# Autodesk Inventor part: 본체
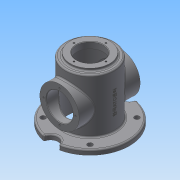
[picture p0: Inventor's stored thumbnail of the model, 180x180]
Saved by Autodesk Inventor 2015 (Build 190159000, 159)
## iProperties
Created: 2018-04
Part Number: 본체
Material: 일반
Document SubType Name: Modeling
Designer: user
Density: 1 g/cm^3
Appearance: 기본값
Mass: 425.882 g
Surface Area: 1203.14 cm^2
Volume: 425.882 cm^3
Author: user
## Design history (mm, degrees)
sketch "스케치2"
  geometry: C1 r 45 at (0, 0); C2 r 50 at (0, 0); 1 further point
  constraints: 2 centre point, 2 coincident
  dimensions: "d0" = 90 diameter of C1; "d1" = 100 diameter of C2
extrude "돌출1" new body sketch "스케치2" distance "d2" = 128; taper "d3" = 0 deg
node "작업 평면1"
sketch "스케치3"
  geometry: L1 (0, 0)-(0, 80); L2 (0, 0)-(0, -80); C1 r 45 at (0, 0); A1 r 15 centre (0, 80) between (-14.934, 78.594) and (14.934, 78.594); A2 r 15 centre (0, -80) between (14.934, -78.594) and (-14.934, -78.594); A3 r 80 centre (0, 0) between (-14.934, 78.594) and (-14.934, -78.594); A4 r 80 centre (0, 0) between (14.934, -78.594) and (14.934, 78.594); A5 r 67.5 centre (0, 0) between (-7.604, 67.07) and (-7.604, -67.07); A6 r 67.5 centre (0, 0) between (7.604, -67.07) and (7.604, 67.07); 1 further point
  constraints: 16 point on circle, 7 centre point, 5 coincident, 4 end point, 2 vertical
  dimensions: "d6" = 90 diameter of C1; "d10" = 30 diameter of A1; "d11" = 30 diameter of A2; "d12" = 80 distance of L1.start L1.end; "d13" = 80 distance of L1.start L2.end; "d14" = 80 radius of A3; "d15" = 67.5 radius of A5; "d16" = 67.5 radius of A6; "d17" = 80 radius of A4
extrude "돌출2" join sketch "스케치3" distance "d18" = 10; taper "d19" = 0 deg
sketch "스케치4"
  geometry: L1 (0, 0)-(-47.73, 47.73); L2 (0, 0)-(-47.73, -47.73); L3 (0, 0)-(0, -36.099); L4 (0, 0)-(47.73, 47.73); L5 (0, 0)-(47.73, -47.73); C1 r 50 at (0, 0) reference; A1 r 67.5 centre (0, 0) between (-47.73, 47.73) and (-47.73, -47.73); 4 further points
  constraints: 10 end point, 5 coincident, 2 point on circle, 2 symmetric about line, 1 centre point, 1 vertical
  dimensions: "d21" = 45 deg angle of L3 L2; "d22" = 90 deg angle of L1 L2; "d23" = 135 diameter of A1
hole "구멍1" sketch "스케치4" at (-47.73, -47.73), (-47.73, 47.73), (47.73, 47.73), (47.73, -47.73) diameter "d24" = 10; stored, may be unused: countersink angle "d28" = 90 deg, drill point angle "d30" = 118 deg; dims "d25" = 6, "d26" = 4, "d27" = 2, "d29" = 8
node "작업 평면2"
sketch "스케치6"
  geometry: C1 r 27 at (0, 0); C2 r 40 at (0, 0); 1 further point
  constraints: 2 centre point, 2 coincident
  dimensions: "d32" = 54 diameter of C1; "d33" = 80 diameter of C2
extrude "돌출3" join sketch "스케치6" distance "d34" = 5; taper "d35" = 0 deg
node "작업 평면3"
sketch "스케치7"
  geometry: C1 r 50 at (0, 0); 1 further point
  constraints: 1 centre point, 1 coincident
  dimensions: "d37" = 100 diameter of C1
extrude "돌출4" join sketch "스케치7" distance "d38" = 8; taper "d39" = 0 deg
extrude "돌출5" cut sketch "스케치6" stored distance "d40" = 8; taper "d41" = 0 deg
node "작업 평면4"
sketch "스케치10"
  geometry: L1 (0, 0)-(0, 68); C1 r 40 at (0, 68); C2 r 27 at (0, 68)
  constraints: 2 centre point, 2 coincident, 2 end point, 1 vertical
  dimensions: "d48" = 68 distance of L1.start L1.end; "d49" = 80 diameter of C1; "d50" = 54 diameter of C2
extrude "돌출6" join sketch "스케치10" stored distance "d51" = 8; taper "d52" = 0 deg
extrude "돌출7" cut sketch "스케치10" stored distance "d53" = 8; taper "d54" = 0 deg
sketch "스케치11"
  geometry: L1 (0, 0)-(0, -32.5); L2 (0, 0)-(32.5, 0); L3 (0, 0)-(-32.5, 0); L4 (0, 0)-(0, 32.5); C1 r 40 at (0, 0) reference; A1 r 32.5 centre (0, 0) between (0, -32.5) and (32.5, 0); 4 further points
  constraints: 8 end point, 5 coincident, 4 point on circle, 2 horizontal, 2 vertical, 1 centre point
  dimensions: "d55" = 65 diameter of A1
hole "구멍2" sketch "스케치11" at (0, -32.5), (-32.5, 0), (0, 32.5), (32.5, 0) diameter "d56" = 3.242; stored, may be unused: countersink angle "d60" = 90 deg, drill point angle "d62" = 118 deg; dims "d57" = 8, "d58" = 4, "d59" = 2, "d61" = 10
sketch "스케치12"
  geometry: L1 (0, 0)-(0, 32.5); L2 (0, 0)-(32.5, 0); L3 (0, 0)-(0, -32.5); L4 (0, 0)-(-32.5, 0); C1 r 40 at (0, 0) reference; A1 r 32.5 centre (0, 0) between (0, 32.5) and (32.5, 0); 5 further points
  constraints: 8 end point, 5 coincident, 4 point on circle, 2 horizontal, 2 vertical, 1 centre point
  dimensions: "d63" = 65 diameter of A1
hole "구멍3" sketch "스케치12" at (0, 32.5), (32.5, 0), (0, -32.5), (-32.5, 0) diameter "d64" = 3.242; stored, may be unused: countersink angle "d68" = 90 deg, drill point angle "d70" = 118 deg; dims "d65" = 8, "d66" = 4, "d67" = 2, "d69" = 10
chamfer "모따기1" distance "d71" = 1; stored, may be unused: second distance "d72" = 2, angle "d73" = 45 deg
fillet "모깎기1" dims "d74" = 3
fillet "모깎기2" dims "d75" = 3
node "작업 평면5"
sketch "스케치13"
  geometry: 2 further points
  constraints: 1 horizontal alignment, 1 other
  dimensions: "d76" = 70 distance of point (0, 0) point (70, 0)
feature "엠보싱1" sketch "스케치13" dims "d77" = 0.5, "d78" = 0
node "솔리드1"
mirror "대칭1"
mirror "대칭2"
other parameters: "d4" = -8, "d7" = 135, "d31" = -133, "d36" = 5, "d47" = 62
